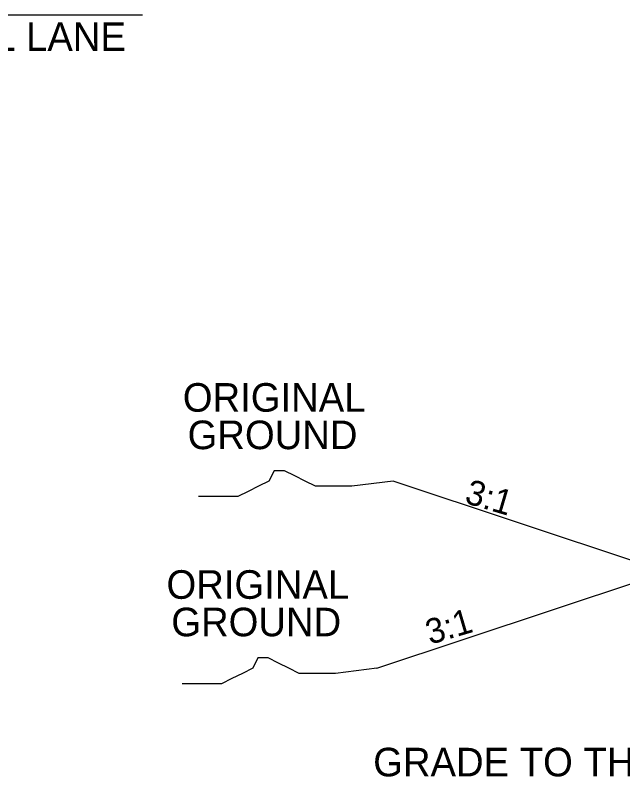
# Model space of a CAD drawing. Extents: x 2176156 to 2177167, y 76401 to 76644.
# Drawn here: x 2176264.04 to 2176288.55, y 76549.85 to 76580.57 of the extents above; entities that cross this region are included whole.
import ezdxf

# ---------------------------------------------------------------- set-up
doc = ezdxf.new("R2010")
doc.units = 0
for name, color, linetype in [('Exist Roads Curbs', 7, 'Continuous'), ('Exist Roads EOP Other', 7, 'Continuous'), ('Exist Structure Minor Culvert Topo', 7, 'Continuous'), ('Old_Level_3', 7, 'Continuous')]:
    doc.layers.add(name, color=color, linetype=linetype)

msp = doc.modelspace()

# ---------------------------------------------------------------- linework, layer by layer
at = {"layer": 'Exist Roads Curbs'}
for points in [[(2176279.287, 76561.772), (2176277.616, 76561.564), (2176277.199, 76561.564), (2176276.571, 76561.564), (2176276.154, 76561.564), (2176275.736, 76561.772), (2176275.318, 76561.981), (2176274.901, 76562.191), (2176274.483, 76562.191), (2176274.273, 76561.772), (2176273.856, 76561.564), (2176273.438, 76561.354), (2176273.021, 76561.146), (2176272.603, 76561.146), (2176272.185, 76561.146), (2176271.768, 76561.146), (2176271.428, 76561.146)], [(2176278.629, 76554.223), (2176276.959, 76554.015), (2176276.541, 76554.015), (2176275.914, 76554.015), (2176275.496, 76554.015), (2176275.078, 76554.223), (2176274.661, 76554.433), (2176274.243, 76554.642), (2176273.825, 76554.642), (2176273.616, 76554.223), (2176273.198, 76554.015), (2176272.78, 76553.805), (2176272.363, 76553.597), (2176271.945, 76553.597), (2176271.527, 76553.597), (2176271.11, 76553.597), (2176270.77, 76553.597)]]:
    msp.add_lwpolyline(points, dxfattribs=at)
at = {"layer": 'Exist Roads EOP Other'}
for p, q in [((2176289.287, 76558.438), (2176279.287, 76561.772)), ((2176278.629, 76554.223), (2176297.239, 76560.426))]:
    msp.add_line(p, q, dxfattribs=at)
at = {"layer": 'Old_Level_3'}
msp.add_line((2176269.17, 76580.568), (2176257.276, 76580.568), dxfattribs=at)

# ---------------------------------------------------------------- texts
at = {"layer": 'Exist Roads Curbs'}
for rotation, p in [(343.5351, (2176282.123, 76560.904)), (16.4649, (2176280.769, 76555.169))]:
    msp.add_text('3:1', height=1.0064, rotation=rotation, dxfattribs=at).set_placement(p)
at = {"layer": 'Exist Structure Minor Culvert Topo'}
for s, height, p in [('TRAVEL LANE', 1.15334, (2176258.045, 76579.127)), ('ORIGINAL', 1.1533, (2176270.796, 76564.573)), ('GROUND', 1.1533, (2176270.99, 76563.062)), ('ORIGINAL', 1.1533, (2176270.138, 76557.025)), ('GROUND', 1.1533, (2176270.332, 76555.513)), ('GRADE TO THIS LINE', 1.15334, (2176278.477, 76549.862))]:
    msp.add_text(s, height=height, dxfattribs=at).set_placement(p)

doc.saveas('drawing.dxf')
